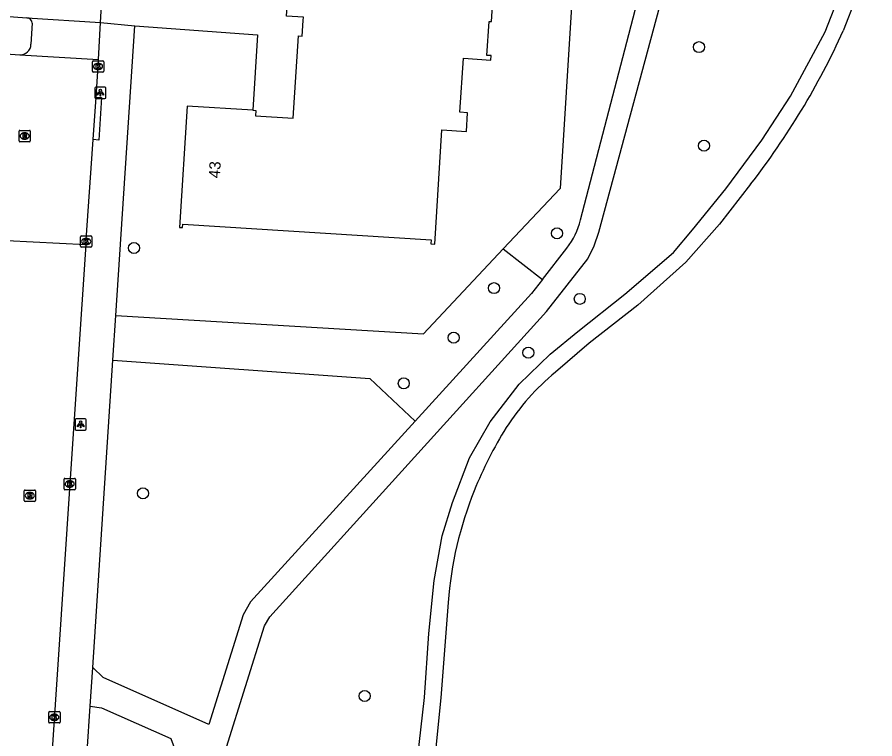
# Model space of a CAD drawing. Extents: x 161848 to 162726, y 385382 to 386521.
# Drawn here: x 162144.6 to 162220.5, y 385931.5 to 385995.3 of the extents above; entities that cross this region are included whole.
import ezdxf

# ---------------------------------------------------------------- set-up
doc = ezdxf.new("R2010")
doc.units = 0
for name, color, linetype in [('IMGEO_Boom', 7, 'Continuous'), ('IMGEO_Groenvoorziening', 7, 'Continuous'), ('IMGEO_Kolk', 7, 'Continuous'), ('IMGEO_Lichtpunt', 7, 'Continuous'), ('IMGEO_Pand', 7, 'Continuous'), ('IMGEO_Pand_nummerreeks', 7, 'Continuous'), ('IMGEO_Rijbaan_lokaal_open', 7, 'Continuous'), ('IMGEO_Rioolput', 7, 'Continuous'), ('IMGEO_Voetpad_halfverhard', 7, 'Continuous'), ('IMGEO_Voetpad_open', 7, 'Continuous'), ('IMGEO_Waterloop', 7, 'Continuous')]:
    doc.layers.add(name, color=color, linetype=linetype)

msp = doc.modelspace()

# ---------------------------------------------------------------- linework, layer by layer
at = {"layer": 'IMGEO_Boom'}
for centre in [(162204.928, 385992.65), (162205.37, 385983.933), (162192.372, 385976.177), (162154.939, 385974.891), (162186.798, 385971.338), (162194.379, 385970.389), (162183.218, 385966.957), (162189.834, 385965.627), (162178.812, 385962.918), (162155.736, 385953.191), (162175.349, 385935.281)]:
    msp.add_circle(centre, 0.489, dxfattribs=at)
at = {"layer": 'IMGEO_Groenvoorziening'}
for points in [[(162190.443, 386005.887), (162194.232, 386005.744), (162192.635, 385980.145), (162187.604, 385974.815)], [(162179.574, 385925.804), (162180.631, 385935.15), (162181.027, 385940.797), (162181.489, 385945.487), (162182.216, 385949.45), (162183.108, 385952.389), (162184.627, 385956.319), (162186.443, 385959.522), (162189.019, 385962.858), (162191.76, 385965.5), (162194.204, 385967.514), (162198.365, 385970.817), (162202.659, 385974.483), (162204.343, 385976.497), (162207.315, 385980.13), (162210.485, 385984.423), (162213.028, 385988.32), (162216.1, 385994.001), (162217.487, 385997.567)], [(162153.342, 385968.931), (162180.563, 385967.297), (162187.604, 385974.815)], [(162187.604, 385974.815), (162191.068, 385972.095)], [(162153.083, 385964.982), (162175.799, 385963.35), (162179.811, 385959.565)]]:
    msp.add_lwpolyline(points, dxfattribs=at)
at = {"layer": 'IMGEO_Kolk'}
for p, q in [((162151.263, 385990.51), (162151.263, 385991.362)), ((162151.338, 385991.436), (162152.19, 385991.436)), ((162151.751, 385991.216), (162151.776, 385991.216)), ((162152.264, 385991.362), (162152.264, 385990.51)), ((162152.19, 385990.436), (162151.338, 385990.436)), ((162151.774, 385990.656), (162151.749, 385990.656)), ((162150.21, 385975.036), (162150.21, 385975.888)), ((162150.285, 385975.962), (162151.137, 385975.962)), ((162150.698, 385975.742), (162150.723, 385975.742)), ((162151.211, 385975.888), (162151.211, 385975.036)), ((162151.137, 385974.962), (162150.285, 385974.962)), ((162150.721, 385975.182), (162150.696, 385975.182)), ((162148.756, 385953.591), (162148.756, 385954.443)), ((162148.831, 385954.517), (162149.683, 385954.517)), ((162149.244, 385954.297), (162149.269, 385954.297)), ((162149.757, 385954.443), (162149.757, 385953.591)), ((162149.683, 385953.517), (162148.831, 385953.517)), ((162149.267, 385953.737), (162149.242, 385953.737)), ((162147.397, 385932.965), (162147.397, 385933.817)), ((162147.472, 385933.891), (162148.324, 385933.891)), ((162147.885, 385933.671), (162147.91, 385933.671)), ((162148.398, 385933.817), (162148.398, 385932.965)), ((162148.324, 385932.891), (162147.472, 385932.891)), ((162147.908, 385933.111), (162147.883, 385933.111))]:
    msp.add_line(p, q, dxfattribs=at)
for points in [[(162151.263, 385990.51), (162151.263, 385991.362)], [(162151.338, 385991.436), (162152.19, 385991.436)], [(162152.264, 385991.362), (162152.264, 385990.51)], [(162152.19, 385990.436), (162151.338, 385990.436)], [(162151.584, 385991.136), (162151.707, 385991.136), (162151.707, 385990.985), (162151.837, 385991.136), (162152.001, 385991.136), (162151.855, 385990.985), (162152.008, 385990.736), (162151.856, 385990.736), (162151.771, 385990.9), (162151.707, 385990.833), (162151.707, 385990.736), (162151.584, 385990.736), (162151.584, 385991.136)], [(162150.21, 385975.036), (162150.21, 385975.888)], [(162150.285, 385975.962), (162151.137, 385975.962)], [(162150.531, 385975.662), (162150.654, 385975.662), (162150.654, 385975.511), (162150.784, 385975.662), (162150.948, 385975.662), (162150.802, 385975.511), (162150.955, 385975.262), (162150.803, 385975.262), (162150.718, 385975.426), (162150.654, 385975.359), (162150.654, 385975.262), (162150.531, 385975.262), (162150.531, 385975.662)], [(162151.211, 385975.888), (162151.211, 385975.036)], [(162151.137, 385974.962), (162150.285, 385974.962)], [(162148.756, 385953.591), (162148.756, 385954.443)], [(162148.831, 385954.517), (162149.683, 385954.517)], [(162149.077, 385954.217), (162149.2, 385954.217), (162149.2, 385954.066), (162149.33, 385954.217), (162149.494, 385954.217), (162149.348, 385954.066), (162149.501, 385953.817), (162149.349, 385953.817), (162149.264, 385953.981), (162149.2, 385953.914), (162149.2, 385953.817), (162149.077, 385953.817), (162149.077, 385954.217)], [(162149.757, 385954.443), (162149.757, 385953.591)], [(162149.683, 385953.517), (162148.831, 385953.517)], [(162147.397, 385932.965), (162147.397, 385933.817)], [(162147.472, 385933.891), (162148.324, 385933.891)], [(162147.718, 385933.591), (162147.841, 385933.591), (162147.841, 385933.44), (162147.971, 385933.591), (162148.135, 385933.591), (162147.989, 385933.44), (162148.142, 385933.191), (162147.99, 385933.191), (162147.905, 385933.355), (162147.841, 385933.288), (162147.841, 385933.191), (162147.718, 385933.191), (162147.718, 385933.591)], [(162148.398, 385933.817), (162148.398, 385932.965)], [(162148.324, 385932.891), (162147.472, 385932.891)]]:
    msp.add_lwpolyline(points, dxfattribs=at)
for centre, start, end in [((162151.34, 385991.36), 91.55205, 178.44795), ((162151.34, 385991.36), 91.55205, 178.44795), ((162152.188, 385991.36), 1.55205, 88.44795), ((162152.188, 385991.36), 1.55205, 88.44795), ((162151.34, 385990.512), 181.55205, 268.44795), ((162151.34, 385990.512), 181.55205, 268.44795), ((162152.188, 385990.512), 271.55205, 358.44795), ((162152.188, 385990.512), 271.55205, 358.44795), ((162150.287, 385975.886), 91.55205, 178.44795), ((162150.287, 385975.886), 91.55205, 178.44795), ((162151.135, 385975.886), 1.55205, 88.44795), ((162151.135, 385975.886), 1.55205, 88.44795), ((162150.287, 385975.038), 181.55205, 268.44795), ((162150.287, 385975.038), 181.55205, 268.44795), ((162151.135, 385975.038), 271.55205, 358.44795), ((162151.135, 385975.038), 271.55205, 358.44795), ((162148.833, 385954.441), 91.55205, 178.44795), ((162148.833, 385954.441), 91.55205, 178.44795), ((162149.681, 385954.441), 1.55205, 88.44795), ((162149.681, 385954.441), 1.55205, 88.44795), ((162148.833, 385953.593), 181.55205, 268.44795), ((162148.833, 385953.593), 181.55205, 268.44795), ((162149.681, 385953.593), 271.55205, 358.44795), ((162149.681, 385953.593), 271.55205, 358.44795), ((162147.474, 385933.815), 91.55205, 178.44795), ((162147.474, 385933.815), 91.55205, 178.44795), ((162148.322, 385933.815), 1.55205, 88.44795), ((162148.322, 385933.815), 1.55205, 88.44795), ((162147.474, 385932.967), 181.55205, 268.44795), ((162147.474, 385932.967), 181.55205, 268.44795), ((162148.322, 385932.967), 271.55205, 358.44795), ((162148.322, 385932.967), 271.55205, 358.44795)]:
    msp.add_arc(centre, 0.0765, start, end, dxfattribs=at)
for centre, major_axis, ratio, start_param, end_param in [((162151.75, 385990.936), (-0.387, 0.002), 0.722429, 4.712389, 7.853982), ((162151.775, 385990.936), (-0.39, 0.002), 0.717154, 1.570796, 4.712389), ((162150.697, 385975.462), (-0.387, 0.002), 0.722429, 4.712389, 7.853982), ((162150.722, 385975.462), (-0.39, 0.002), 0.717154, 1.570796, 4.712389), ((162149.243, 385954.017), (-0.387, 0.002), 0.722429, 4.712389, 7.853982), ((162149.268, 385954.017), (-0.39, 0.002), 0.717154, 1.570796, 4.712389), ((162147.884, 385933.391), (-0.387, 0.002), 0.722429, 4.712389, 7.853982), ((162147.909, 385933.391), (-0.39, 0.002), 0.717154, 1.570796, 4.712389)]:
    msp.add_ellipse(centre, major_axis=major_axis, ratio=ratio, start_param=start_param, end_param=end_param, dxfattribs=at)
at = {"layer": 'IMGEO_Lichtpunt'}
for p, q in [((162151.47, 385989.021), (162151.47, 385988.214)), ((162151.47, 385989.021), (162151.47, 385988.214)), ((162152.372, 385989.116), (162151.564, 385989.116)), ((162152.372, 385989.116), (162151.564, 385989.116)), ((162152.466, 385988.214), (162152.466, 385989.021)), ((162152.466, 385988.214), (162152.466, 385989.021)), ((162151.564, 385988.12), (162152.372, 385988.12)), ((162151.564, 385988.12), (162152.372, 385988.12)), ((162149.726, 385959.693), (162149.726, 385958.886)), ((162149.726, 385959.693), (162149.726, 385958.886)), ((162150.628, 385959.788), (162149.82, 385959.788)), ((162150.628, 385959.788), (162149.82, 385959.788)), ((162150.722, 385958.886), (162150.722, 385959.693)), ((162150.722, 385958.886), (162150.722, 385959.693)), ((162149.82, 385958.792), (162150.628, 385958.792)), ((162149.82, 385958.792), (162150.628, 385958.792))]:
    msp.add_line(p, q, dxfattribs=at)
for points in [[(162151.844, 385988.685), (162151.883, 385988.657), (162151.695, 385988.395), (162151.657, 385988.422), (162151.844, 385988.685)], [(162151.946, 385988.637), (162151.993, 385988.637), (162151.993, 385988.315), (162151.946, 385988.315), (162151.946, 385988.637)], [(162152.056, 385988.657), (162152.094, 385988.684), (162152.281, 385988.422), (162152.242, 385988.394), (162152.056, 385988.657)], [(162150.1, 385959.357), (162150.139, 385959.329), (162149.951, 385959.067), (162149.913, 385959.094), (162150.1, 385959.357)], [(162150.312, 385959.329), (162150.35, 385959.356), (162150.537, 385959.094), (162150.498, 385959.066), (162150.312, 385959.329)], [(162150.202, 385959.309), (162150.249, 385959.309), (162150.249, 385958.987), (162150.202, 385958.987), (162150.202, 385959.309)]]:
    msp.add_lwpolyline(points, dxfattribs=at)
for centre in [(162151.969, 385988.819), (162150.225, 385959.491)]:
    msp.add_circle(centre, 0.0994, dxfattribs=at)
for centre, start, end in [((162151.564, 385989.021), 90, 180), ((162151.564, 385989.021), 90, 180), ((162152.372, 385989.021), 0, 90), ((162152.372, 385989.021), 0, 90), ((162151.564, 385988.214), 180, 270), ((162151.564, 385988.214), 180, 270), ((162152.372, 385988.214), 270, 0), ((162152.372, 385988.214), 270, 360), ((162149.82, 385959.693), 90, 180), ((162149.82, 385959.693), 90, 180), ((162150.628, 385959.693), 0, 90), ((162150.628, 385959.693), 0, 90), ((162149.82, 385958.886), 180, 270), ((162149.82, 385958.886), 180, 270), ((162150.628, 385958.886), 270, 0), ((162150.628, 385958.886), 270, 360)]:
    msp.add_arc(centre, 0.0946, start, end, dxfattribs=at)
at = {"layer": 'IMGEO_Pand'}
for points in [[(162165.451, 385987.069), (162159.652, 385987.435), (162158.974, 385976.703), (162159.245, 385976.685), (162159.265, 385976.993), (162181.228, 385975.605), (162181.206, 385975.259), (162181.549, 385975.237), (162182.187, 385985.339), (162184.348, 385985.202), (162184.452, 385986.843), (162183.782, 385986.885), (162184.083, 385991.658), (162186.505, 385991.505), (162186.53, 385991.9), (162186.164, 385991.923), (162186.354, 385994.92), (162186.584, 385994.906), (162186.906, 386000), (162187.099, 386003.058), (162186.84, 386003.075), (162187.013, 386005.809), (162190.424, 386005.593), (162190.443, 386005.887)], [(162165.451, 385987.069), (162165.733, 385987.051), (162165.703, 385986.582), (162169.032, 385986.372), (162169.491, 385993.636), (162169.828, 385993.614), (162169.916, 385995), (162169.935, 385995.3), (162168.441, 385995.395), (162168.603, 385997.957), (162168.611, 385998.086)]]:
    msp.add_lwpolyline(points, dxfattribs=at)
at = {"layer": 'IMGEO_Rijbaan_lokaal_open'}
for points in [[(162151.991, 385994.826), (162152.317, 386000.392)], [(162072.445, 385996.95), (162078.632, 385996.529), (162120.807, 385993.662), (162130.556, 385992.978), (162144.838, 385991.962)], [(162129.655, 385996.426), (162145.477, 385995.243)], [(162145.477, 385995.243), (162151.991, 385994.826)], [(162145.948, 385994.778), (162145.827, 385992.896)], [(162151.8, 385991.555), (162151.991, 385994.826)], [(162144.838, 385991.962), (162151.8, 385991.555)], [(162151.583, 385988.219), (162151.765, 385990.953), (162151.8, 385991.555)], [(162151.333, 385984.469), (162151.583, 385988.219)], [(162150.691, 385975.187), (162151.333, 385984.469)], [(162143.703, 385975.556), (162150.691, 385975.187)], [(162150.691, 385975.187), (162149.256, 385954.021), (162146.681, 385914.982), (162145.383, 385895.531), (162142.706, 385855.491), (162140.044, 385815.501), (162138.772, 385796.328), (162135.705, 385751.411)]]:
    msp.add_lwpolyline(points, dxfattribs=at)
for centre, radius, start, end in [((162145.436, 385994.73), 0.515, 5.33867, 85.39588), ((162144.878, 385992.91), 0.949, 267.5667, 359.15674)]:
    msp.add_arc(centre, radius, start, end, dxfattribs=at)
at = {"layer": 'IMGEO_Rioolput'}
for p, q in [((162144.771, 385984.362), (162144.771, 385985.214)), ((162144.846, 385985.288), (162145.698, 385985.288)), ((162145.772, 385985.214), (162145.772, 385984.362)), ((162145.282, 385984.508), (162145.257, 385984.508)), ((162145.259, 385985.068), (162145.284, 385985.068)), ((162145.698, 385984.288), (162144.846, 385984.288)), ((162145.228, 385952.56), (162145.228, 385953.412)), ((162145.303, 385953.486), (162146.155, 385953.486)), ((162145.716, 385953.266), (162145.741, 385953.266)), ((162146.229, 385953.412), (162146.229, 385952.56)), ((162145.739, 385952.706), (162145.714, 385952.706)), ((162146.155, 385952.486), (162145.303, 385952.486))]:
    msp.add_line(p, q, dxfattribs=at)
for points in [[(162144.771, 385984.362), (162144.771, 385985.214)], [(162144.846, 385985.288), (162145.698, 385985.288)], [(162145.772, 385985.214), (162145.772, 385984.362)], [(162145.36, 385984.986), (162145.108, 385984.988), (162145.108, 385984.588)], [(162145.108, 385984.588), (162145.232, 385984.588), (162145.232, 385984.75), (162145.243, 385984.75)], [(162145.286, 385984.907), (162145.232, 385984.907), (162145.232, 385984.826)], [(162145.232, 385984.826), (162145.284, 385984.826)], [(162145.29, 385984.721), (162145.361, 385984.588), (162145.501, 385984.588), (162145.436, 385984.714)], [(162145.698, 385984.288), (162144.846, 385984.288)], [(162145.228, 385952.56), (162145.228, 385953.412)], [(162145.303, 385953.486), (162146.155, 385953.486)], [(162146.229, 385953.412), (162146.229, 385952.56)], [(162145.817, 385953.184), (162145.565, 385953.186), (162145.565, 385952.786)], [(162145.565, 385952.786), (162145.689, 385952.786), (162145.689, 385952.948), (162145.7, 385952.948)], [(162145.743, 385953.105), (162145.689, 385953.105), (162145.689, 385953.024)], [(162145.689, 385953.024), (162145.741, 385953.024)], [(162145.747, 385952.919), (162145.818, 385952.786), (162145.958, 385952.786), (162145.893, 385952.912)], [(162146.155, 385952.486), (162145.303, 385952.486)]]:
    msp.add_lwpolyline(points, dxfattribs=at)
for centre, radius, start, end in [((162144.848, 385985.212), 0.0765, 91.55205, 178.44795), ((162144.848, 385985.212), 0.0765, 91.55205, 178.44795), ((162145.696, 385985.212), 0.0765, 1.55205, 88.44795), ((162145.696, 385985.212), 0.0765, 1.55205, 88.44795), ((162144.848, 385984.364), 0.0765, 181.55205, 268.44795), ((162144.848, 385984.364), 0.0765, 181.55205, 268.44795), ((162145.242, 385984.697), 0.0533, 26.02933, 88.69889), ((162145.268, 385985.015), 0.19, 274.7715, 282.96867), ((162145.292, 385984.811), 0.0964, 77.00612, 93.18647), ((162145.306, 385984.868), 0.0378, 276.66336, 79.67722), ((162145.359, 385984.876), 0.109, 350.36119, 89.41601), ((162145.357, 385984.876), 0.112, 277.58423, 350.98172), ((162145.341, 385984.661), 0.108, 29.51342, 73.79051), ((162145.696, 385984.364), 0.0765, 271.55205, 358.44795), ((162145.696, 385984.364), 0.0765, 271.55205, 358.44795), ((162145.305, 385953.41), 0.0765, 91.55205, 178.44795), ((162145.305, 385953.41), 0.0765, 91.55205, 178.44795), ((162146.153, 385953.41), 0.0765, 1.55205, 88.44795), ((162146.153, 385953.41), 0.0765, 1.55205, 88.44795), ((162145.305, 385952.562), 0.0765, 181.55205, 268.44795), ((162145.305, 385952.562), 0.0765, 181.55205, 268.44795), ((162145.699, 385952.895), 0.0533, 26.02933, 88.69889), ((162145.725, 385953.213), 0.19, 274.7715, 282.96867), ((162145.749, 385953.009), 0.0964, 77.00612, 93.18647), ((162145.763, 385953.066), 0.0378, 276.66336, 79.67722), ((162145.816, 385953.074), 0.109, 350.36119, 89.41601), ((162145.814, 385953.074), 0.112, 277.58423, 350.98172), ((162145.798, 385952.859), 0.108, 29.51342, 73.79051), ((162146.153, 385952.562), 0.0765, 271.55205, 358.44795), ((162146.153, 385952.562), 0.0765, 271.55205, 358.44795)]:
    msp.add_arc(centre, radius, start, end, dxfattribs=at)
for centre, major_axis, ratio, start_param, end_param in [((162145.258, 385984.788), (-0.387, 0.002), 0.722429, 4.712389, 7.853982), ((162145.283, 385984.788), (-0.39, 0.002), 0.717154, 1.570796, 4.712389), ((162145.715, 385952.986), (-0.387, 0.002), 0.722429, 4.712389, 7.853982), ((162145.74, 385952.986), (-0.39, 0.002), 0.717154, 1.570796, 4.712389)]:
    msp.add_ellipse(centre, major_axis=major_axis, ratio=ratio, start_param=start_param, end_param=end_param, dxfattribs=at)
at = {"layer": 'IMGEO_Voetpad_halfverhard'}
for points in [[(162159.557, 385805.784), (162158.695, 385864.488), (162158.9, 385868.909), (162163.127, 385930.755), (162166.494, 385941.466), (162166.953, 385942.268), (162191.432, 385969.273), (162195.081, 385973.92), (162195.654, 385975.073), (162196.057, 385976.295), (162202.458, 386000), (162212.322, 386037.98)], [(162194.442, 385977.376), (162200.349, 386000), (162207.39, 386026.963)], [(162191.068, 385972.095), (162193.247, 385974.87)], [(162191.068, 385972.095), (162190.101, 385970.863), (162179.811, 385959.565)], [(162179.811, 385959.565), (162165.262, 385943.59), (162164.612, 385942.442), (162161.577, 385932.746), (162152.21, 385936.914), (162151.3, 385937.797)], [(162151.07, 385934.388), (162152.081, 385934.218), (162158.196, 385931.518), (162158.672, 385930.26), (162158.191, 385922.998), (162160.071, 385922.868), (162159.484, 385913.888)]]:
    msp.add_lwpolyline(points, dxfattribs=at)
msp.add_arc((162187.852, 385978.981), 6.783, 322.69555, 346.31565, dxfattribs=at)
at = {"layer": 'IMGEO_Voetpad_open'}
for points in [[(162151.991, 385994.826), (162155.02, 385994.519)], [(162153.342, 385968.931), (162155.02, 385994.519)], [(162155.02, 385994.519), (162165.878, 385993.729), (162165.451, 385987.069)], [(162151.583, 385988.219), (162152.076, 385988.182), (162151.821, 385984.433), (162151.333, 385984.469)], [(162153.083, 385964.982), (162153.342, 385968.931)], [(162151.3, 385937.797), (162153.083, 385964.982)], [(162151.07, 385934.388), (162151.3, 385937.797)], [(162149.729, 385914.341), (162151.07, 385934.388)]]:
    msp.add_lwpolyline(points, dxfattribs=at)
at = {"layer": 'IMGEO_Waterloop'}
for points in [[(162220.483, 386001.25), (162219.995, 386000), (162217.693, 385994.101)], [(162209.497, 385980.521), (162206.731, 385976.997), (162203.77, 385973.635), (162199.511, 385969.824), (162195.202, 385966.481), (162192.218, 385963.895)], [(162182.725, 385943.542), (162182.102, 385935.109), (162180.602, 385920.392), (162179.262, 385894.577), (162178.816, 385888.175), (162178.001, 385862.984), (162178.03, 385855.675), (162177.6, 385842.344), (162177.129, 385815.735), (162176.868, 385812.284), (162176.867, 385800.819), (162176.867, 385800.784), (162176.862, 385760.126), (162176.657, 385753.475), (162176.783, 385750), (162176.854, 385748.052)]]:
    msp.add_lwpolyline(points, dxfattribs=at)
for centre, radius, start, end in [((162155.581, 386022.325), 68.224, 322.21202, 335.56311), ((162205.789, 385947.427), 21.339, 129.49202, 147.12598), ((162218.696, 385939.897), 36.273, 148.20245, 158.10256), ((162216.384, 385940.87), 33.765, 158.17174, 175.46163)]:
    msp.add_arc(centre, radius, start, end, dxfattribs=at)

# ---------------------------------------------------------------- texts
at = {"layer": 'IMGEO_Pand_nummerreeks'}
msp.add_text('43', height=1, rotation=86.38485, dxfattribs=at).set_placement((162162.534, 385981.038))

doc.saveas('drawing.dxf')
